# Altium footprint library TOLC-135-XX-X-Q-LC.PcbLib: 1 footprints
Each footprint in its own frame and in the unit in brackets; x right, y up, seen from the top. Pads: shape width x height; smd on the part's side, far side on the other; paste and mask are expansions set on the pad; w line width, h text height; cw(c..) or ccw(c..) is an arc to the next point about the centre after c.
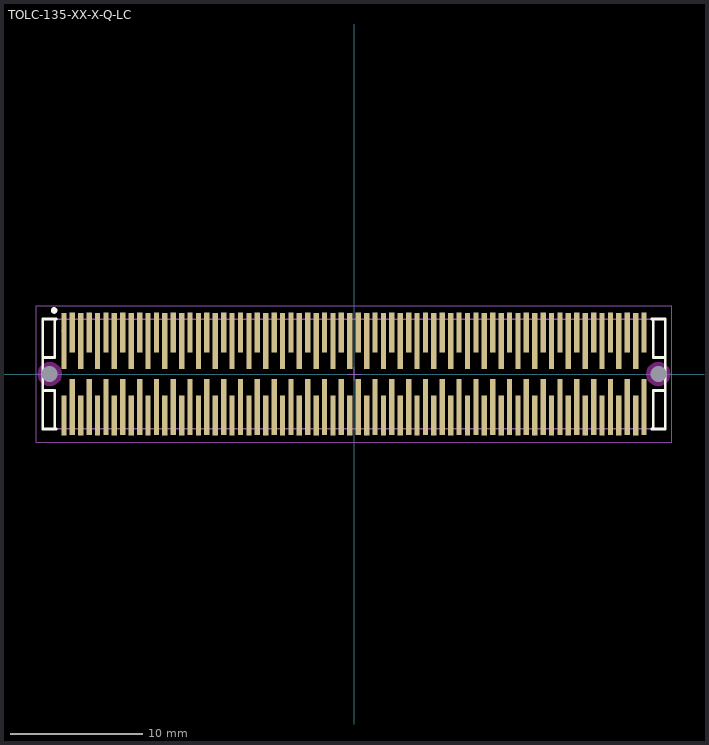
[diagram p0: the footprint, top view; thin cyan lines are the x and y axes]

## TOLC-135-XX-X-Q-LC [mm] "1.27mm pitch, 140 pin, terminal strip; 4 rows, w/locking clips, SMT"
height 5.59
pads (142):
  rect 0.4x4.25 smd mask+0: 1(-21.907,2.5) 4(-21.273,-2.5) 5(-20.637,2.5) 8(-20.002,-2.5) 9(-19.367,2.5) 12(-18.732,-2.5) 13(-18.098,2.5) 16(-17.462,-2.5) 17(-16.828,2.5) 20(-16.192,-2.5) 21(-15.557,2.5) 24(-14.922,-2.5) 25(-14.287,2.5) 28(-13.652,-2.5) 29(-13.018,2.5) 32(-12.383,-2.5) 33(-11.747,2.5) 36(-11.112,-2.5) 37(-10.477,2.5) 40(-9.842,-2.5) 41(-9.207,2.5) 44(-8.572,-2.5) 45(-7.938,2.5) 48(-7.302,-2.5) 49(-6.667,2.5) 52(-6.032,-2.5) 53(-5.397,2.5) 56(-4.763,-2.5) 57(-4.127,2.5) 60(-3.492,-2.5) 61(-2.857,2.5) 64(-2.222,-2.5) 65(-1.587,2.5) 68(-0.953,-2.5) 69(-0.318,2.5) 72(0.318,-2.5) 73(0.953,2.5) 76(1.587,-2.5) 77(2.222,2.5) 80(2.857,-2.5) 81(3.492,2.5) 84(4.127,-2.5) 85(4.763,2.5) 88(5.397,-2.5) 89(6.032,2.5) 92(6.667,-2.5) 93(7.302,2.5) 96(7.938,-2.5) 97(8.572,2.5) 100(9.207,-2.5) 101(9.842,2.5) 104(10.477,-2.5) 105(11.112,2.5) 108(11.747,-2.5) 109(12.383,2.5) 112(13.018,-2.5) 113(13.652,2.5) 116(14.287,-2.5) 117(14.922,2.5) 120(15.557,-2.5) 121(16.192,2.5) 124(16.828,-2.5) 125(17.462,2.5) 128(18.098,-2.5) 129(18.732,2.5) 132(19.367,-2.5) 133(20.002,2.5) 136(20.637,-2.5) 137(21.273,2.5) 140(21.907,-2.5)
  rect 0.4x3 smd mask+0: 2(-21.907,-3.135) 3(-21.273,3.135) 6(-20.637,-3.135) 7(-20.002,3.135) 10(-19.367,-3.135) 11(-18.732,3.135) 14(-18.098,-3.135) 15(-17.462,3.135) 18(-16.828,-3.135) 19(-16.192,3.135) 22(-15.557,-3.135) 23(-14.922,3.135) 26(-14.287,-3.135) 27(-13.652,3.135) 30(-13.018,-3.135) 31(-12.383,3.135) 34(-11.747,-3.135) 35(-11.112,3.135) 38(-10.477,-3.135) 39(-9.842,3.135) 42(-9.207,-3.135) 43(-8.572,3.135) 46(-7.938,-3.135) 47(-7.302,3.135) 50(-6.667,-3.135) 51(-6.032,3.135) 54(-5.397,-3.135) 55(-4.763,3.135) 58(-4.127,-3.135) 59(-3.492,3.135) 62(-2.857,-3.135) 63(-2.222,3.135) 66(-1.587,-3.135) 67(-0.953,3.135) 70(-0.318,-3.135) 71(0.318,3.135) 74(0.953,-3.135) 75(1.587,3.135) 78(2.222,-3.135) 79(2.857,3.135) 82(3.492,-3.135) 83(4.127,3.135) 86(4.763,-3.135) 87(5.397,3.135) 90(6.032,-3.135) 91(6.667,3.135) 94(7.302,-3.135) 95(7.938,3.135) 98(8.572,-3.135) 99(9.207,3.135) 102(9.842,-3.135) 103(10.477,3.135) 106(11.112,-3.135) 107(11.747,3.135) 110(12.383,-3.135) 111(13.018,3.135) 114(13.652,-3.135) 115(14.287,3.135) 118(14.922,-3.135) 119(15.557,3.135) 122(16.192,-3.135) 123(16.828,3.135) 126(17.462,-3.135) 127(18.098,3.135) 130(18.732,-3.135) 131(19.367,3.135) 134(20.002,-3.135) 135(20.637,3.135) 138(21.273,-3.135) 139(21.907,3.135)
  round 1 hole 1.2 unplated mask+0: 141(-22.987,0) 142(22.987,0)
Top Overlay:
  circle w0.25: c-22.65,4.8 r0.125
  lines w0.2: -23.5,-1.25 -22.6,-1.25 -22.6,-4.15 ; -23.5,1.25 -22.6,1.25 -22.6,4.15 ; -22.5,-4.15 -23.5,-4.15 -23.5,4.15 -22.5,4.15 ; 22.5,-4.15 23.5,-4.15 23.5,4.15 22.5,4.15 ; 22.6,-4.15 22.6,-1.25 23.5,-1.25 ; 22.6,4.15 22.6,1.25 23.5,1.25
Keep-Out Layer:
  pour cut-out: -22.079,0 -22.11,0.235 -22.201,0.454 -22.345,0.642 -22.533,0.786 -22.752,0.877 -22.987,0.908 -23.222,0.877 -23.441,0.786 -23.629,0.642 -23.773,0.454 -23.864,0.235 -23.895,0 -23.864,-0.235 -23.773,-0.454 -23.629,-0.642 -23.441,-0.786 -23.222,-0.877 -22.987,-0.908 -22.752,-0.877 -22.533,-0.786 -22.345,-0.642 -22.201,-0.454 -22.11,-0.235
  pour cut-out: 23.895,0 23.864,0.235 23.773,0.454 23.629,0.642 23.441,0.786 23.222,0.877 22.987,0.908 22.752,0.877 22.533,0.786 22.345,0.642 22.201,0.454 22.11,0.235 22.079,0 22.11,-0.235 22.201,-0.454 22.345,-0.642 22.533,-0.786 22.752,-0.877 22.987,-0.908 23.222,-0.877 23.441,-0.786 23.629,-0.642 23.773,-0.454 23.864,-0.235
Mechanical 12:
  lines w0.001: -23.5,-4.15 -23.5,4.15 23.5,4.15 23.5,-4.15 -23.5,-4.15 ; -23.5,-1.25 -22.6,-1.25 -22.6,-4.15 22.6,-4.15 22.6,-1.25 23.495,-1.25 23.495,1.25 22.6,1.25 22.6,4.15 -22.6,4.15 -22.6,1.25 -23.5,1.25 -23.5,-1.25
Mechanical 13:
  circle w0.1: c-21.924,3.265 r0.127
  lines w0.1: -23.5,-4.15 -23.5,4.15 23.5,4.15 23.5,-4.15 -23.5,-4.15 ; -23.5,-1.25 -22.6,-1.25 -22.6,-4.15 22.6,-4.15 22.6,-1.25 23.495,-1.25 23.495,1.25 22.6,1.25 22.6,4.15 -22.6,4.15 -22.6,1.25 -23.5,1.25 -23.5,-1.25
  text ".Designator" at 0,-0.127 h1.52
Mechanical 15:
  lines w0.05: -0.5,0 0.5,0 ; 0,-0.5 0,0.5 ; -24,-5.15 24,-5.15 24,5.15 -24,5.15 -24,-5.15
Mechanical 16:
  circle w0.001: c-21.924,3.265 r0.127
